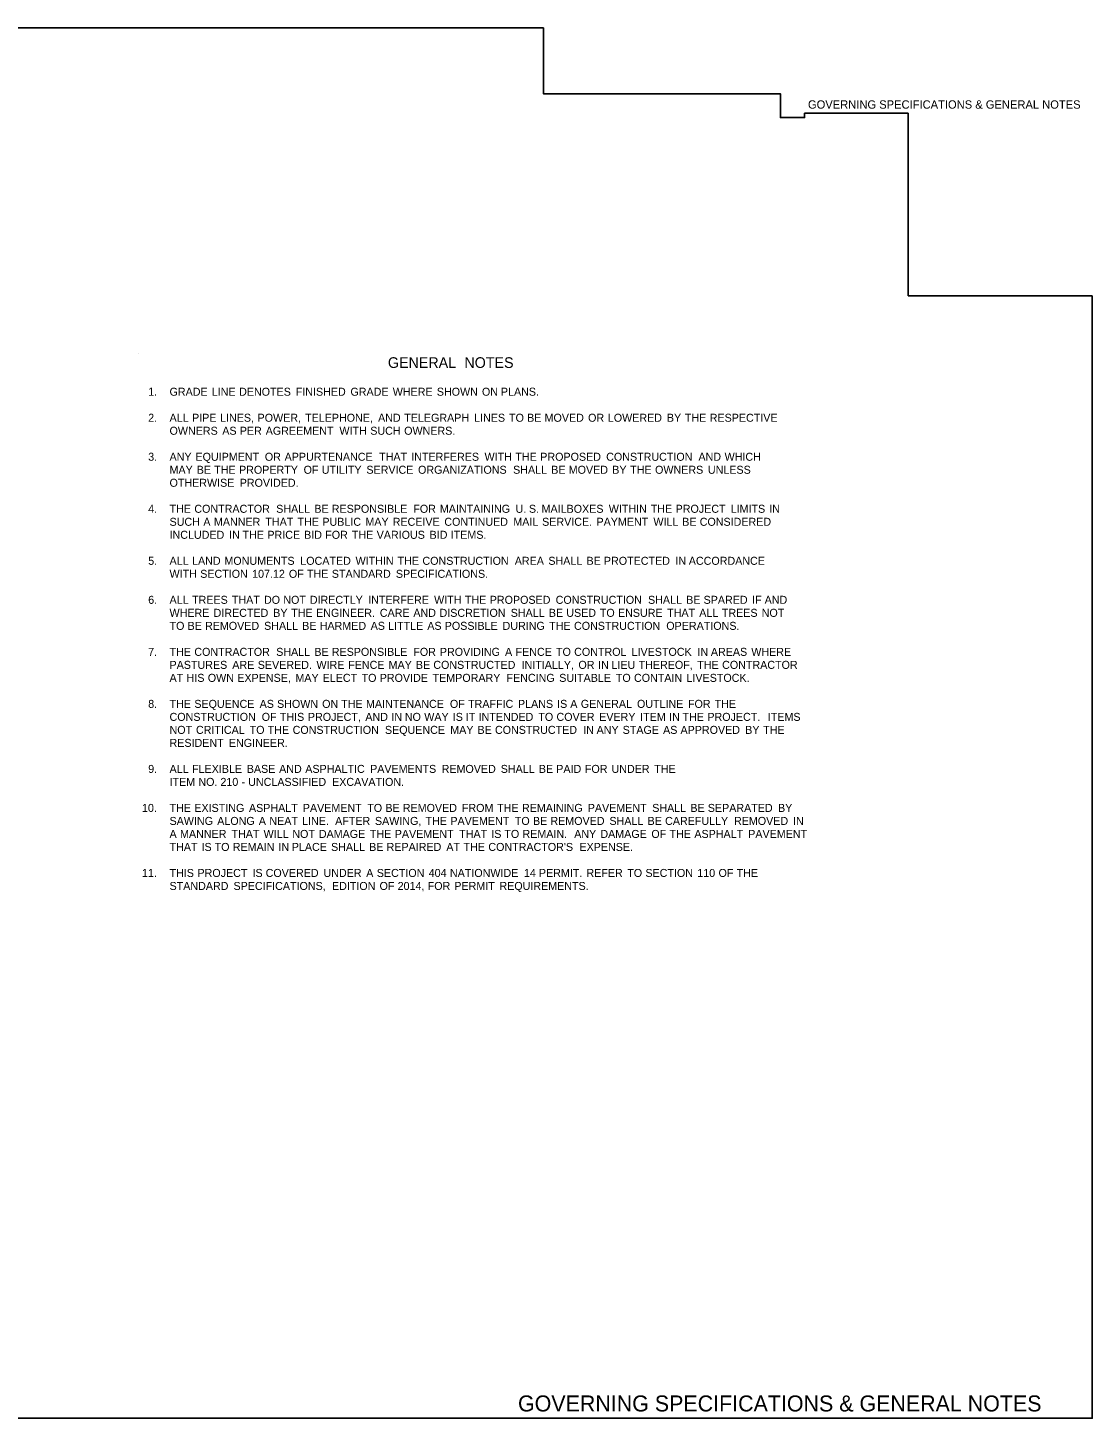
# Model space of a CAD drawing. Extents: x 1955683 to 1956002, y 566394 to 566602.
# Drawn here: x 1955842.9 to 1956002.5, y 566393.5 to 566602 of the extents above; entities that cross this region are included whole.
import ezdxf

# ---------------------------------------------------------------- set-up
doc = ezdxf.new("R2010")
doc.units = 0
for name, color, linetype in [('Default', 7, 'Continuous'), ('R_Border', 7, 'Continuous'), ('R_Border Prem', 7, 'Continuous'), ('STAMP', 7, 'Continuous')]:
    doc.layers.add(name, color=color, linetype=linetype)

msp = doc.modelspace()

# ---------------------------------------------------------------- linework, layer by layer
at = {"layer": 'R_Border'}
msp.add_line((1955859.48, 566553.1), (1955859.48, 566553.1), dxfattribs=at)
at = {"layer": 'R_Border Prem'}
for points in [[(1956002.45, 566561.79), (1956002.45, 566393.51), (1955683.38, 566393.51), (1955683.38, 566601.97), (1955920.19, 566601.97), (1955920.19, 566592.09), (1955955.71, 566592.09), (1955955.71, 566588.52), (1955959.35, 566588.52), (1955959.35, 566589.17), (1955974.89, 566589.17)], [(1955974.89, 566589.17), (1955974.89, 566561.79), (1956002.45, 566561.79)]]:
    msp.add_lwpolyline(points, dxfattribs=at)

# ---------------------------------------------------------------- texts
at = {"layer": 'Default'}
for s, height, p in [('GENERAL', 1.6, (1955896.89, 566550.98)), (' NOTES', 1.6, (1955907.76, 566550.98)), ('1.', 1.2, (1955860.96, 566546.81)), ('GRADE', 1.2, (1955864.16, 566546.81)), (' LINE', 1.2, (1955870.04, 566546.81)), (' DENOTES', 1.2, (1955874.14, 566546.81)), (' FINISHED', 1.2, (1955882.63, 566546.81)), (' GRADE', 1.2, (1955890.83, 566546.81)), (' WHERE', 1.2, (1955897.17, 566546.81)), (' SHOWN', 1.2, (1955903.78, 566546.81)), (' ON', 1.2, (1955910.54, 566546.81)), (' PLANS.', 1.2, (1955913.38, 566546.81)), ('2.', 1.2, (1955860.96, 566542.91)), ('ALL', 1.2, (1955864.16, 566542.91)), (' PIPE', 1.2, (1955867.09, 566542.91)), (' LINES,', 1.2, (1955871.29, 566542.91)), (' POWER,', 1.2, (1955876.91, 566542.91)), (' TELEPHONE,', 1.2, (1955884.03, 566542.91)), (' AND', 1.2, (1955894.97, 566542.91)), (' TELEGRAPH', 1.2, (1955898.89, 566542.91)), (' LINES', 1.2, (1955909.37, 566542.91)), (' TO', 1.2, (1955914.6, 566542.91)), (' BE', 1.2, (1955917.31, 566542.91)), (' MOVED', 1.2, (1955919.93, 566542.91)), (' OR', 1.2, (1955926.45, 566542.91)), (' LOWERED', 1.2, (1955929.41, 566542.91)), (' BY', 1.2, (1955938.26, 566542.91)), (' THE', 1.2, (1955940.95, 566542.91)), (' RESPECTIVE', 1.2, (1955944.68, 566542.91)), ('OWNERS', 1.2, (1955864.16, 566540.96)), (' AS', 1.2, (1955871.62, 566540.96)), (' PER', 1.2, (1955874.24, 566540.96)), (' AGREEMENT', 1.2, (1955878.13, 566540.96)), (' WITH', 1.2, (1955889.18, 566540.96)), (' SUCH', 1.2, (1955893.8, 566540.96)), (' OWNERS.', 1.2, (1955898.88, 566540.96)), ('3.', 1.2, (1955860.96, 566537.06)), ('ANY', 1.2, (1955864.16, 566537.06)), (' EQUIPMENT', 1.2, (1955867.6, 566537.06)), (' OR', 1.2, (1955878, 566537.06)), (' APPURTENANCE', 1.2, (1955880.96, 566537.06)), (' THAT', 1.2, (1955895.13, 566537.06)), (' INTERFERES', 1.2, (1955899.94, 566537.06)), (' WITH', 1.2, (1955910.93, 566537.06)), (' THE', 1.2, (1955915.55, 566537.06)), (' PROPOSED', 1.2, (1955919.28, 566537.06)), (' CONSTRUCTION', 1.2, (1955929.16, 566537.06)), (' AND', 1.2, (1955942.99, 566537.06)), (' WHICH', 1.2, (1955946.91, 566537.06)), ('MAY', 1.2, (1955864.16, 566535.11)), (' BE', 1.2, (1955867.79, 566535.11)), (' THE', 1.2, (1955870.4, 566535.11)), (' PROPERTY', 1.2, (1955874.13, 566535.11)), (' OF', 1.2, (1955883.81, 566535.11)), (' UTILITY', 1.2, (1955886.52, 566535.11)), (' SERVICE', 1.2, (1955893.22, 566535.11)), (' ORGANIZATIONS', 1.2, (1955900.96, 566535.11)), (' SHALL', 1.2, (1955915.21, 566535.11)), (' BE', 1.2, (1955920.93, 566535.11)), (' MOVED', 1.2, (1955923.55, 566535.11)), (' BY', 1.2, (1955930.07, 566535.11)), (' THE', 1.2, (1955932.76, 566535.11)), (' OWNERS', 1.2, (1955936.49, 566535.11)), (' UNLESS', 1.2, (1955944.41, 566535.11)), ('OTHERWISE', 1.2, (1955864.16, 566533.16)), (' PROVIDED.', 1.2, (1955874.23, 566533.16)), ('4.', 1.2, (1955860.96, 566529.26)), ('THE', 1.2, (1955864.16, 566529.26)), (' CONTRACTOR', 1.2, (1955867.43, 566529.26)), (' SHALL', 1.2, (1955879.7, 566529.26)), (' BE', 1.2, (1955885.42, 566529.26)), (' RESPONSIBLE', 1.2, (1955888.03, 566529.26)), (' FOR', 1.2, (1955900.25, 566529.26)), (' MAINTAINING', 1.2, (1955904.23, 566529.26)), (' U.', 1.2, (1955915.58, 566529.26)), (' S.', 1.2, (1955917.58, 566529.26)), (' MAILBOXES', 1.2, (1955919.48, 566529.26)), (' WITHIN', 1.2, (1955929.55, 566529.26)), (' THE', 1.2, (1955935.84, 566529.26)), (' PROJECT', 1.2, (1955939.57, 566529.26)), (' LIMITS', 1.2, (1955947.82, 566529.26)), (' IN', 1.2, (1955953.6, 566529.26)), ('SUCH', 1.2, (1955864.16, 566527.31)), (' A', 1.2, (1955868.78, 566527.31)), (' MANNER', 1.2, (1955870.37, 566527.31)), (' THAT', 1.2, (1955878.08, 566527.31)), (' THE', 1.2, (1955882.89, 566527.31)), (' PUBLIC', 1.2, (1955886.62, 566527.31)), (' MAY', 1.2, (1955893.07, 566527.31)), (' RECEIVE', 1.2, (1955897.16, 566527.31)), (' CONTINUED', 1.2, (1955904.9, 566527.31)), (' MAIL', 1.2, (1955915.24, 566527.31)), (' SERVICE.', 1.2, (1955919.56, 566527.31)), (' PAYMENT', 1.2, (1955927.71, 566527.31)), (' WILL', 1.2, (1955936.24, 566527.31)), (' BE', 1.2, (1955940.56, 566527.31)), (' CONSIDERED', 1.2, (1955943.18, 566527.31)), ('INCLUDED', 1.2, (1955864.16, 566525.36)), (' IN', 1.2, (1955872.65, 566525.36)), (' THE', 1.2, (1955874.65, 566525.36)), (' PRICE', 1.2, (1955878.38, 566525.36)), (' BID', 1.2, (1955883.88, 566525.36)), (' FOR', 1.2, (1955887.05, 566525.36)), (' THE', 1.2, (1955891.03, 566525.36)), (' VARIOUS', 1.2, (1955894.76, 566525.36)), (' BID', 1.2, (1955902.69, 566525.36)), (' ITEMS.', 1.2, (1955905.86, 566525.36)), ('5.', 1.2, (1955860.96, 566521.46)), ('ALL', 1.2, (1955864.16, 566521.46)), ('WITH', 1.2, (1955864.16, 566519.51)), (' LAND', 1.2, (1955867.09, 566521.46)), (' SECTION', 1.2, (1955868.31, 566519.51)), (' MONUMENTS', 1.2, (1955871.94, 566521.46)), (' 107.12', 1.2, (1955876.09, 566519.51)), (' OF', 1.2, (1955881.6, 566519.51)), (' LOCATED', 1.2, (1955883.31, 566521.46)), (' THE', 1.2, (1955884.31, 566519.51)), (' STANDARD', 1.2, (1955888.04, 566519.51)), (' WITHIN', 1.2, (1955891.6, 566521.46)), (' SPECIFICATIONS.', 1.2, (1955897.64, 566519.51)), (' THE', 1.2, (1955897.89, 566521.46)), (' CONSTRUCTION', 1.2, (1955901.62, 566521.46)), (' AREA', 1.2, (1955915.46, 566521.46)), (' SHALL', 1.2, (1955920.49, 566521.46)), (' BE', 1.2, (1955926.21, 566521.46)), (' PROTECTED', 1.2, (1955928.82, 566521.46)), (' IN', 1.2, (1955939.54, 566521.46)), (' ACCORDANCE', 1.2, (1955941.54, 566521.46)), ('6.', 1.2, (1955860.96, 566515.61)), ('ALL', 1.2, (1955864.16, 566515.61)), (' TREES', 1.2, (1955867.09, 566515.61)), (' THAT', 1.2, (1955873.06, 566515.61)), (' DO', 1.2, (1955877.87, 566515.61)), (' NOT', 1.2, (1955880.77, 566515.61)), (' DIRECTLY', 1.2, (1955884.74, 566515.61)), (' INTERFERE', 1.2, (1955893.49, 566515.61)), (' WITH', 1.2, (1955903.37, 566515.61)), (' THE', 1.2, (1955907.98, 566515.61)), (' PROPOSED', 1.2, (1955911.71, 566515.61)), (' CONSTRUCTION', 1.2, (1955921.59, 566515.61)), (' SHALL', 1.2, (1955935.43, 566515.61)), (' BE', 1.2, (1955941.15, 566515.61)), (' SPARED', 1.2, (1955943.76, 566515.61)), (' IF', 1.2, (1955951.03, 566515.61)), (' AND', 1.2, (1955952.91, 566515.61)), ('WHERE', 1.2, (1955864.16, 566513.66)), (' DIRECTED', 1.2, (1955870.32, 566513.66)), (' BY', 1.2, (1955879.26, 566513.66)), (' THE', 1.2, (1955881.95, 566513.66)), (' ENGINEER.', 1.2, (1955885.68, 566513.66)), (' CARE', 1.2, (1955895.23, 566513.66)), (' AND', 1.2, (1955900.26, 566513.66)), (' DISCRETION', 1.2, (1955904.18, 566513.66)), (' SHALL', 1.2, (1955914.85, 566513.66)), (' BE', 1.2, (1955920.57, 566513.66)), (' USED', 1.2, (1955923.18, 566513.66)), (' TO', 1.2, (1955928.21, 566513.66)), (' ENSURE', 1.2, (1955930.93, 566513.66)), (' THAT', 1.2, (1955938.3, 566513.66)), (' ALL', 1.2, (1955943.11, 566513.66)), (' TREES', 1.2, (1955946.5, 566513.66)), (' NOT', 1.2, (1955952.47, 566513.66)), ('TO', 1.2, (1955864.16, 566511.71)), (' BE', 1.2, (1955866.42, 566511.71)), (' REMOVED', 1.2, (1955869.03, 566511.71)), (' SHALL', 1.2, (1955877.89, 566511.71)), (' BE', 1.2, (1955883.6, 566511.71)), (' HARMED', 1.2, (1955886.22, 566511.71)), (' AS', 1.2, (1955893.86, 566511.71)), (' LITTLE', 1.2, (1955896.48, 566511.71)), (' AS', 1.2, (1955902.35, 566511.71)), (' POSSIBLE', 1.2, (1955904.96, 566511.71)), (' DURING', 1.2, (1955913.63, 566511.71)), (' THE', 1.2, (1955920.61, 566511.71)), (' CONSTRUCTION', 1.2, (1955924.34, 566511.71)), (' OPERATIONS.', 1.2, (1955938.17, 566511.71)), ('7.', 1.2, (1955860.96, 566507.81)), ('THE', 1.2, (1955864.16, 566507.81)), (' CONTRACTOR', 1.2, (1955867.43, 566507.81)), (' SHALL', 1.2, (1955879.7, 566507.81)), (' BE', 1.2, (1955885.42, 566507.81)), (' RESPONSIBLE', 1.2, (1955888.03, 566507.81)), (' FOR', 1.2, (1955900.25, 566507.81)), (' PROVIDING', 1.2, (1955904.23, 566507.81)), (' A', 1.2, (1955914, 566507.81)), (' FENCE', 1.2, (1955915.58, 566507.81)), (' TO', 1.2, (1955921.64, 566507.81)), (' CONTROL', 1.2, (1955924.36, 566507.81)), (' LIVESTOCK', 1.2, (1955932.97, 566507.81)), (' IN', 1.2, (1955942.84, 566507.81)), (' AREAS', 1.2, (1955944.85, 566507.81)), (' WHERE', 1.2, (1955950.91, 566507.81)), ('PASTURES', 1.2, (1955864.16, 566505.86)), (' ARE', 1.2, (1955873.12, 566505.86)), (' SEVERED.', 1.2, (1955876.94, 566505.86)), (' WIRE', 1.2, (1955885.74, 566505.86)), (' FENCE', 1.2, (1955890.49, 566505.86)), (' MAY', 1.2, (1955896.55, 566505.86)), (' BE', 1.2, (1955900.64, 566505.86)), (' CONSTRUCTED', 1.2, (1955903.25, 566505.86)), (' INITIALLY,', 1.2, (1955916.48, 566505.86)), (' OR', 1.2, (1955925, 566505.86)), (' IN', 1.2, (1955927.96, 566505.86)), (' LIEU', 1.2, (1955929.96, 566505.86)), (' THEREOF,', 1.2, (1955934.02, 566505.86)), (' THE', 1.2, (1955942.81, 566505.86)), (' CONTRACTOR', 1.2, (1955946.54, 566505.86)), ('AT', 1.2, (1955864.16, 566503.91)), (' HIS', 1.2, (1955866.27, 566503.91)), (' OWN', 1.2, (1955869.45, 566503.91)), (' EXPENSE,', 1.2, (1955873.87, 566503.91)), (' MAY', 1.2, (1955882.58, 566503.91)), (' ELECT', 1.2, (1955886.66, 566503.91)), (' TO', 1.2, (1955892.5, 566503.91)), (' PROVIDE', 1.2, (1955895.22, 566503.91)), (' TEMPORARY', 1.2, (1955903.14, 566503.91)), (' FENCING', 1.2, (1955914.22, 566503.91)), (' SUITABLE', 1.2, (1955922.12, 566503.91)), (' TO', 1.2, (1955930.61, 566503.91)), (' CONTAIN', 1.2, (1955933.33, 566503.91)), (' LIVESTOCK.', 1.2, (1955941.2, 566503.91)), ('8.', 1.2, (1955860.96, 566500.01)), ('THE', 1.2, (1955864.16, 566500.01)), (' SEQUENCE', 1.2, (1955867.43, 566500.01)), (' AS', 1.2, (1955877.22, 566500.01)), (' SHOWN', 1.2, (1955879.83, 566500.01)), (' ON', 1.2, (1955886.59, 566500.01)), (' THE', 1.2, (1955889.43, 566500.01)), (' MAINTENANCE', 1.2, (1955893.16, 566500.01)), (' OF', 1.2, (1955905.74, 566500.01)), (' TRAFFIC', 1.2, (1955908.46, 566500.01)), (' PLANS', 1.2, (1955915.94, 566500.01)), (' IS', 1.2, (1955921.81, 566500.01)), (' A', 1.2, (1955923.78, 566500.01)), (' GENERAL', 1.2, (1955925.36, 566500.01)), (' OUTLINE', 1.2, (1955933.78, 566500.01)), (' FOR', 1.2, (1955941.42, 566500.01)), (' THE', 1.2, (1955945.41, 566500.01)), ('CONSTRUCTION', 1.2, (1955864.16, 566498.06)), (' OF', 1.2, (1955877.53, 566498.06)), (' THIS', 1.2, (1955880.25, 566498.06)), (' PROJECT,', 1.2, (1955884.45, 566498.06)), (' AND', 1.2, (1955893.06, 566498.06)), (' IN', 1.2, (1955896.97, 566498.06)), (' NO', 1.2, (1955898.98, 566498.06)), (' WAY', 1.2, (1955901.89, 566498.06)), (' IS', 1.2, (1955906.16, 566498.06)), (' IT', 1.2, (1955908.12, 566498.06)), (' INTENDED', 1.2, (1955910.04, 566498.06)), (' TO', 1.2, (1955918.99, 566498.06)), (' COVER', 1.2, (1955921.71, 566498.06)), (' EVERY', 1.2, (1955928.11, 566498.06)), (' ITEM', 1.2, (1955934.25, 566498.06)), (' IN', 1.2, (1955938.6, 566498.06)), (' THE', 1.2, (1955940.6, 566498.06)), (' PROJECT.', 1.2, (1955944.33, 566498.06)), ('  ITEMS', 1.2, (1955952.94, 566498.06)), ('NOT', 1.2, (1955864.16, 566496.11)), (' CRITICAL', 1.2, (1955867.67, 566496.11)), (' TO', 1.2, (1955875.72, 566496.11)), (' THE', 1.2, (1955878.43, 566496.11)), (' CONSTRUCTION', 1.2, (1955882.16, 566496.11)), (' SEQUENCE', 1.2, (1955896, 566496.11)), (' MAY', 1.2, (1955905.79, 566496.11)), (' BE', 1.2, (1955909.87, 566496.11)), (' CONSTRUCTED', 1.2, (1955912.49, 566496.11)), (' IN', 1.2, (1955925.72, 566496.11)), (' ANY', 1.2, (1955927.72, 566496.11)), (' STAGE', 1.2, (1955931.63, 566496.11)), (' AS', 1.2, (1955937.69, 566496.11)), (' APPROVED', 1.2, (1955940.3, 566496.11)), (' BY', 1.2, (1955950, 566496.11)), (' THE', 1.2, (1955952.69, 566496.11)), ('RESIDENT', 1.2, (1955864.16, 566494.16)), (' ENGINEER.', 1.2, (1955872.61, 566494.16)), ('9.', 1.2, (1955860.96, 566490.26)), ('ALL', 1.2, (1955864.16, 566490.26)), (' FLEXIBLE', 1.2, (1955867.09, 566490.26)), (' BASE', 1.2, (1955875.29, 566490.26)), (' AND', 1.2, (1955880.14, 566490.26)), (' ASPHALTIC', 1.2, (1955884.06, 566490.26)), (' PAVEMENTS', 1.2, (1955893.78, 566490.26)), (' REMOVED', 1.2, (1955904.5, 566490.26)), (' SHALL', 1.2, (1955913.35, 566490.26)), (' BE', 1.2, (1955919.07, 566490.26)), (' PAID', 1.2, (1955921.68, 566490.26)), (' FOR', 1.2, (1955925.97, 566490.26)), (' UNDER', 1.2, (1955929.96, 566490.26)), (' THE', 1.2, (1955936.36, 566490.26)), ('ITEM', 1.2, (1955864.16, 566488.31)), (' NO.', 1.2, (1955868.04, 566488.31)), (' 210', 1.2, (1955871.34, 566488.31)), (' UNCLASSIFIED', 1.2, (1955875.5, 566488.31)), (' EXCAVATION.', 1.2, (1955888.08, 566488.31)), (' -', 1.2, (1955874.52, 566488.31)), ('10.', 1.2, (1955860.03, 566484.41)), ('THE', 1.2, (1955864.16, 566484.41)), (' EXISTING', 1.2, (1955867.43, 566484.41)), (' ASPHALT', 1.2, (1955875.62, 566484.41)), (' PAVEMENT', 1.2, (1955883.69, 566484.41)), (' TO', 1.2, (1955893.35, 566484.41)), (' BE', 1.2, (1955896.07, 566484.41)), (' REMOVED', 1.2, (1955898.68, 566484.41)), (' FROM', 1.2, (1955907.53, 566484.41)), (' THE', 1.2, (1955912.81, 566484.41)), (' REMAINING', 1.2, (1955916.54, 566484.41)), (' PAVEMENT', 1.2, (1955926.4, 566484.41)), (' SHALL', 1.2, (1955936.06, 566484.41)), (' BE', 1.2, (1955941.78, 566484.41)), (' SEPARATED', 1.2, (1955944.39, 566484.41)), (' BY', 1.2, (1955954.92, 566484.41)), ('SAWING', 1.2, (1955864.16, 566482.46)), (' ALONG', 1.2, (1955870.86, 566482.46)), (' A', 1.2, (1955877.09, 566482.46)), (' NEAT', 1.2, (1955878.68, 566482.46)), (' LINE.', 1.2, (1955883.58, 566482.46)), ('  AFTER', 1.2, (1955888.09, 566482.46)), (' SAWING,', 1.2, (1955894.5, 566482.46)), (' THE', 1.2, (1955902.08, 566482.46)), (' PAVEMENT', 1.2, (1955905.81, 566482.46)), (' TO', 1.2, (1955915.47, 566482.46)), (' BE', 1.2, (1955918.19, 566482.46)), (' REMOVED', 1.2, (1955920.8, 566482.46)), (' SHALL', 1.2, (1955929.65, 566482.46)), (' BE', 1.2, (1955935.37, 566482.46)), (' CAREFULLY', 1.2, (1955937.99, 566482.46)), (' REMOVED', 1.2, (1955948.32, 566482.46)), (' IN', 1.2, (1955957.17, 566482.46)), ('A', 1.2, (1955864.16, 566480.51)), (' MANNER', 1.2, (1955865.29, 566480.51)), (' THAT', 1.2, (1955873, 566480.51)), (' WILL', 1.2, (1955877.81, 566480.51)), (' NOT', 1.2, (1955882.12, 566480.51)), (' DAMAGE', 1.2, (1955886.09, 566480.51)), (' THE', 1.2, (1955893.74, 566480.51)), (' PAVEMENT', 1.2, (1955897.47, 566480.51)), (' THAT', 1.2, (1955907.13, 566480.51)), (' IS', 1.2, (1955911.94, 566480.51)), (' TO', 1.2, (1955913.9, 566480.51)), (' REMAIN.', 1.2, (1955916.62, 566480.51)), ('  ANY', 1.2, (1955923.92, 566480.51)), (' DAMAGE', 1.2, (1955928.29, 566480.51)), (' OF', 1.2, (1955935.93, 566480.51)), (' THE', 1.2, (1955938.65, 566480.51)), (' ASPHALT', 1.2, (1955942.38, 566480.51)), (' PAVEMENT', 1.2, (1955950.45, 566480.51)), ('THAT', 1.2, (1955864.16, 566478.56)), (' IS', 1.2, (1955868.51, 566478.56)), (' TO', 1.2, (1955870.47, 566478.56)), (' REMAIN', 1.2, (1955873.19, 566478.56)), (' IN', 1.2, (1955880.04, 566478.56)), (' PLACE', 1.2, (1955882.04, 566478.56)), (' SHALL', 1.2, (1955887.92, 566478.56)), (' BE', 1.2, (1955893.64, 566478.56)), (' REPAIRED', 1.2, (1955896.25, 566478.56)), (' AT', 1.2, (1955905.2, 566478.56)), (' THE', 1.2, (1955907.77, 566478.56)), (" CONTRACTOR'S", 1.2, (1955911.5, 566478.56)), (' EXPENSE.', 1.2, (1955925.15, 566478.56)), ('11.', 1.2, (1955860.03, 566474.66)), ('THIS', 1.2, (1955864.16, 566474.66)), (' PROJECT', 1.2, (1955867.9, 566474.66)), (' IS', 1.2, (1955876.15, 566474.66)), (' COVERED', 1.2, (1955878.12, 566474.66)), (' UNDER', 1.2, (1955886.79, 566474.66)), (' A', 1.2, (1955893.19, 566474.66)), (' SECTION', 1.2, (1955894.78, 566474.66)), (' 404', 1.2, (1955902.56, 566474.66)), (' NATIONWIDE', 1.2, (1955905.74, 566474.66)), (' 14', 1.2, (1955916.83, 566474.66)), (' PERMIT.', 1.2, (1955919.08, 566474.66)), (' REFER', 1.2, (1955926.2, 566474.66)), (' TO', 1.2, (1955932.32, 566474.66)), (' SECTION', 1.2, (1955935.04, 566474.66)), (' 110', 1.2, (1955942.82, 566474.66)), (' OF', 1.2, (1955946, 566474.66)), (' THE', 1.2, (1955948.72, 566474.66)), ('STANDARD', 1.2, (1955864.16, 566472.71)), (' SPECIFICATIONS,', 1.2, (1955873.3, 566472.71)), (' EDITION', 1.2, (1955888.06, 566472.71)), (' OF', 1.2, (1955895.19, 566472.71)), (' 2014,', 1.2, (1955897.9, 566472.71)), (' FOR', 1.2, (1955902.41, 566472.71)), (' PERMIT', 1.2, (1955906.4, 566472.71)), (' REQUIREMENTS.', 1.2, (1955913.16, 566472.71))]:
    msp.add_text(s, height=height, dxfattribs=at).set_placement(p)
at = {"layer": 'R_Border'}
msp.add_text('GOVERNING SPECIFICATIONS & GENERAL NOTES', height=2.4, rotation=0, dxfattribs=at).set_placement((1955916.39, 566394.52))
at = {"layer": 'STAMP'}
msp.add_text('GOVERNING SPECIFICATIONS & GENERAL NOTES', height=1.25, rotation=360, dxfattribs=at).set_placement((1955959.85, 566589.85))

doc.saveas('drawing.dxf')
